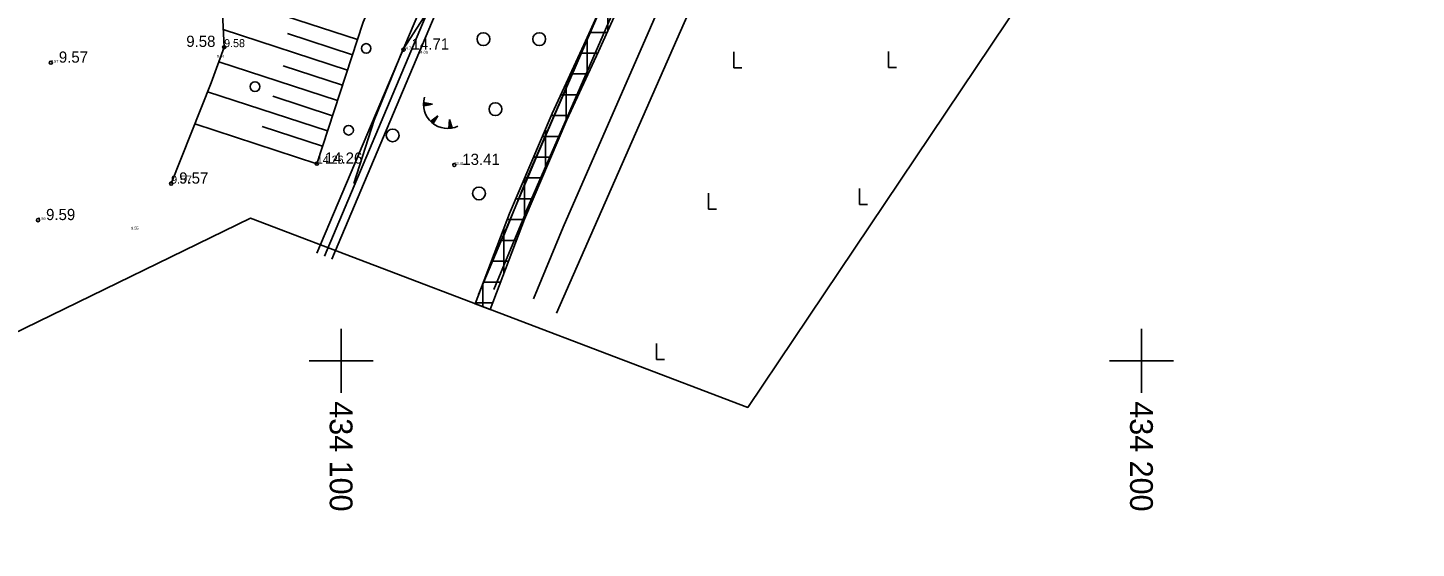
# Model space of a CAD drawing. Extents: x 433497 to 434382, y 6534486 to 6534993.
# Drawn here: x 434060.9 to 434234.3, y 6534676.6 to 6534741.6 of the extents above; entities that cross this region are included whole.
import ezdxf

# ---------------------------------------------------------------- set-up
doc = ezdxf.new("R2010")
doc.units = 0
for name, color, linetype in [('HALJASTUS', 7, 'Continuous'), ('Kaitsevöönd', 7, 'Continuous'), ('kataster', 7, 'Continuous'), ('KORGUS-EH2000', 7, 'Continuous'), ('MOOTKORG-EH2000', 7, 'Continuous'), ('PIIR', 7, 'Continuous'), ('RELJEEF', 7, 'Continuous'), ('TEE', 7, 'Continuous'), ('VORK', 7, 'Continuous'), ('VORMISTUS', 7, 'Continuous')]:
    doc.layers.add(name, color=color, linetype=linetype)

msp = doc.modelspace()

# ---------------------------------------------------------------- linework, layer by layer
at = {"layer": 'HALJASTUS'}
for p, q in [((434149.09, 6534738.6), (434149.09, 6534736.6)), ((434168.39, 6534738.64), (434168.39, 6534736.64)), ((434149.09, 6534736.6), (434150.09, 6534736.6)), ((434168.39, 6534736.64), (434169.39, 6534736.64)), ((434145.91, 6534720.93), (434145.91, 6534718.93)), ((434164.77, 6534721.53), (434164.77, 6534719.53)), ((434145.91, 6534718.93), (434146.91, 6534718.93)), ((434164.77, 6534719.53), (434165.77, 6534719.53)), ((434139.4, 6534702.16), (434139.4, 6534700.16)), ((434139.4, 6534700.16), (434140.4, 6534700.16))]:
    msp.add_line(p, q, dxfattribs=at)
msp.add_lwpolyline([(434120.17, 6534715.22), (434123.29, 6534722.97), (434138.26, 6534757.49), (434144.61, 6534770.46), (434146.07, 6534772.24), (434145.28, 6534773.04), (434138, 6534768.94), (434126.49, 6534763.78), (434119.61, 6534756.79), (434114.78, 6534749.84), (434107.73, 6534738.86), (434104.13, 6534730.07), (434101.6, 6534722.14)], dxfattribs=at)
for centre, radius in [((434103.14, 6534739.03), 0.6), ((434117.79, 6534740.19), 0.8), ((434124.76, 6534740.19), 0.8), ((434089.24, 6534734.26), 0.6), ((434119.29, 6534731.44), 0.8), ((434100.94, 6534728.81), 0.6), ((434106.44, 6534728.16), 0.8), ((434117.24, 6534720.91), 0.8)]:
    msp.add_circle(centre, radius, dxfattribs=at)
at = {"layer": 'Kaitsevöönd'}
for p, q in [((434133.33, 6534741.22), (434133.33, 6534746.11)), ((434131.06, 6534741.04), (434133.25, 6534741.04)), ((434130.73, 6534735.52), (434130.73, 6534740.31)), ((434129.88, 6534738.44), (434132.08, 6534738.44)), ((434128.68, 6534735.84), (434130.88, 6534735.84)), ((434128.13, 6534729.88), (434128.13, 6534734.66)), ((434127.47, 6534733.24), (434129.68, 6534733.24)), ((434126.28, 6534730.64), (434128.47, 6534730.64)), ((434125.53, 6534723.82), (434125.53, 6534728.89)), ((434125.16, 6534728.04), (434127.34, 6534728.04)), ((434124.05, 6534725.44), (434126.22, 6534725.44)), ((434122.93, 6534722.84), (434125.11, 6534722.84)), ((434122.93, 6534717.76), (434122.93, 6534722.83)), ((434121.82, 6534720.24), (434123.99, 6534720.24)), ((434120.74, 6534717.64), (434122.88, 6534717.64)), ((434119.76, 6534715.04), (434121.9, 6534715.04)), ((434120.33, 6534710.9), (434120.33, 6534716.56)), ((434118.77, 6534712.44), (434120.91, 6534712.44)), ((434117.79, 6534709.84), (434119.93, 6534709.84)), ((434117.73, 6534706.77), (434117.73, 6534709.68)), ((434116.77, 6534707.13), (434118.63, 6534706.42)), ((434116.81, 6534707.24), (434118.94, 6534707.24))]:
    msp.add_line(p, q, dxfattribs=at)
for points in [[(434128.22, 6534730.09), (434132.17, 6534738.64), (434136.03, 6534747.25), (434138.36, 6534752.33), (434142.93, 6534762.75), (434145.46, 6534769.14), (434146.37, 6534771.61), (434148.65, 6534776.78), (434150.92, 6534781.96), (434153.22, 6534787.21), (434154.72, 6534791.75), (434156.63, 6534795.9), (434159.88, 6534804.56), (434163.81, 6534814.84), (434168.18, 6534825.41), (434171.94, 6534834.07), (434175.51, 6534841.48), (434180.59, 6534850.69), (434185.97, 6534861.25), (434188.69, 6534866.23), (434193.78, 6534875.18), (434200.73, 6534887.95), (434203.32, 6534892.68)], [(434134.21, 6534748.07), (434130.35, 6534739.46), (434126.39, 6534730.89), (434121.03, 6534718.41), (434116.77, 6534707.13)], [(434118.63, 6534706.42), (434122.9, 6534717.68), (434128.22, 6534730.09)]]:
    msp.add_lwpolyline(points, dxfattribs=at)
at = {"layer": 'kataster'}
for points in [[(434117.18, 6534708.3), (434124.43, 6534725.5), (434148.55, 6534781.24), (434178.98, 6534849.69), (434202.39, 6534892.23)], [(434218.02, 6534802.56), (434170.81, 6534805.85), (434126.93, 6534705.93)]]:
    msp.add_lwpolyline(points, dxfattribs=at)
at = {"layer": 'KORGUS-EH2000'}
for centre in [(434085.39, 6534739.19), (434107.81, 6534738.88), (434063.74, 6534737.25), (434096.97, 6534724.63), (434114.15, 6534724.47), (434078.77, 6534722.14), (434062.14, 6534717.58)]:
    msp.add_circle(centre, 0.2, dxfattribs=at)
at = {"layer": 'PIIR'}
for points in [[(434096.98, 6534713.46), (434111.2, 6534747.09), (434125.92, 6534777.86), (434134.17, 6534794.4)], [(434097.91, 6534713.07), (434112.11, 6534746.68), (434126.82, 6534777.42), (434134.89, 6534793.6)], [(434098.83, 6534712.69), (434113.02, 6534746.27), (434127.72, 6534776.99), (434136.48, 6534794.54)]]:
    msp.add_lwpolyline(points, dxfattribs=at)
at = {"layer": 'RELJEEF'}
for p, q in [((434102.04, 6534740.13), (434085.33, 6534745.59)), ((434100.8, 6534736.33), (434085.28, 6534741.4)), ((434093.3, 6534740.88), (434101.42, 6534738.23)), ((434099.55, 6534732.52), (434084.73, 6534737.37)), ((434092.78, 6534736.84), (434100.18, 6534734.42)), ((434098.31, 6534728.72), (434083.32, 6534733.62)), ((434091.49, 6534733.06), (434098.93, 6534730.62)), ((434111.42, 6534732.05), (434110.3, 6534732.27)), ((434110.3, 6534732.2), (434110.37, 6534732.26)), ((434110.3, 6534732.14), (434110.43, 6534732.24)), ((434110.3, 6534732.07), (434110.49, 6534732.23)), ((434110.3, 6534732.01), (434110.56, 6534732.22)), ((434110.3, 6534731.95), (434110.62, 6534732.21)), ((434110.3, 6534731.88), (434110.69, 6534732.19)), ((434111.42, 6534732.05), (434110.3, 6534731.84)), ((434110.32, 6534731.84), (434110.75, 6534732.18)), ((434110.43, 6534731.86), (434110.82, 6534732.17)), ((434110.54, 6534731.88), (434110.88, 6534732.16)), ((434110.64, 6534731.9), (434110.95, 6534732.14)), ((434110.75, 6534731.92), (434111.01, 6534732.13)), ((434110.85, 6534731.94), (434111.07, 6534732.12)), ((434110.96, 6534731.96), (434111.14, 6534732.11)), ((434111.07, 6534731.99), (434111.2, 6534732.09)), ((434111.17, 6534732.01), (434111.27, 6534732.08)), ((434112.08, 6534730.61), (434111.19, 6534729.91)), ((434111.28, 6534732.03), (434111.33, 6534732.07)), ((434112.08, 6534730.61), (434111.52, 6534729.63)), ((434096.97, 6534724.63), (434081.73, 6534729.61)), ((434090.14, 6534729.29), (434097.69, 6534726.82)), ((434111.24, 6534729.86), (434111.24, 6534729.95)), ((434111.29, 6534729.82), (434111.29, 6534729.99)), ((434111.34, 6534729.78), (434111.34, 6534730.03)), ((434111.38, 6534729.73), (434111.4, 6534730.07)), ((434111.43, 6534729.7), (434111.45, 6534730.11)), ((434111.48, 6534729.66), (434111.5, 6534730.15)), ((434111.53, 6534729.65), (434111.55, 6534730.19)), ((434111.58, 6534729.74), (434111.6, 6534730.23)), ((434111.64, 6534729.83), (434111.65, 6534730.28)), ((434111.69, 6534729.93), (434111.7, 6534730.32)), ((434111.74, 6534730.02), (434111.76, 6534730.36)), ((434111.8, 6534730.12), (434111.81, 6534730.4)), ((434111.85, 6534730.21), (434111.86, 6534730.44)), ((434111.9, 6534730.3), (434111.91, 6534730.48)), ((434111.96, 6534730.4), (434111.96, 6534730.52)), ((434112.01, 6534730.49), (434112.01, 6534730.56)), ((434113.54, 6534730.17), (434113.46, 6534729.03)), ((434113.53, 6534729.04), (434113.46, 6534729.1)), ((434113.66, 6534729.05), (434113.47, 6534729.23)), ((434113.59, 6534729.04), (434113.47, 6534729.16)), ((434113.78, 6534729.07), (434113.48, 6534729.36)), ((434113.72, 6534729.06), (434113.48, 6534729.3)), ((434113.88, 6534729.11), (434113.49, 6534729.49)), ((434113.84, 6534729.08), (434113.49, 6534729.43)), ((434113.82, 6534729.31), (434113.5, 6534729.62)), ((434113.85, 6534729.21), (434113.5, 6534729.56)), ((434113.75, 6534729.52), (434113.51, 6534729.75)), ((434113.78, 6534729.41), (434113.51, 6534729.69)), ((434113.69, 6534729.72), (434113.52, 6534729.88)), ((434113.72, 6534729.62), (434113.52, 6534729.82)), ((434113.62, 6534729.93), (434113.53, 6534730.02)), ((434113.65, 6534729.83), (434113.53, 6534729.95)), ((434113.54, 6534730.17), (434113.89, 6534729.09)), ((434113.59, 6534730.03), (434113.54, 6534730.08))]:
    msp.add_line(p, q, dxfattribs=at)
for points in [[(434129.41, 6534765.84), (434122.95, 6534765.01), (434118.16, 6534761.86), (434113.49, 6534758.38), (434108.22, 6534753.42), (434105.41, 6534748.46), (434102.76, 6534742.33), (434096.97, 6534724.63)], [(434078.77, 6534722.14), (434083.76, 6534734.73), (434085.39, 6534739.19), (434085.15, 6534744.27), (434085.55, 6534747.13), (434086.6, 6534750.63), (434088.2, 6534754.58), (434090.45, 6534762.42), (434094.01, 6534764.84)]]:
    msp.add_lwpolyline(points, dxfattribs=at)
msp.add_arc((434113.32, 6534732.06), 3.03, 163.4234, 295.1745, dxfattribs=at)
at = {"layer": 'TEE'}
for points in [[(434119.09, 6534708.9), (434123.12, 6534718.63), (434123.12, 6534718.64), (434123.13, 6534718.66), (434123.14, 6534718.68), (434134.06, 6534743.67), (434144.32, 6534767.16), (434146.02, 6534771.11)], [(434150.71, 6534769.33), (434148.93, 6534765.18), (434148.93, 6534765.18), (434148.92, 6534765.17), (434148.92, 6534765.17), (434138.66, 6534741.66), (434138.66, 6534741.66), (434127.75, 6534716.7), (434124.04, 6534707.73)]]:
    msp.add_lwpolyline(points, dxfattribs=at)
at = {"layer": 'VORK'}
for p, q in [((434100, 6534704), (434100, 6534696)), ((434200, 6534704), (434200, 6534696)), ((434096, 6534700), (434104, 6534700)), ((434196, 6534700), (434204, 6534700))]:
    msp.add_line(p, q, dxfattribs=at)
at = {"layer": 'VORMISTUS'}
msp.add_lwpolyline([(434004.05, 6534676.58), (434088.7, 6534717.82), (434150.82, 6534694.17), (434223.11, 6534801.87), (434234.34, 6534880.46), (434217.51, 6534886.64), (434161.53, 6534910.47), (434143, 6534925.08), (434107.19, 6534919.58), (434105.08, 6534919.64), (434021.47, 6534961.7)], dxfattribs=at)
msp.add_lwpolyline([(434004.05, 6534676.58), (434088.7, 6534717.82), (434150.82, 6534694.17), (434223.11, 6534801.87), (434234.34, 6534880.46), (434217.51, 6534886.64), (434161.53, 6534910.47), (434143, 6534925.08), (434107.19, 6534919.58), (434105.08, 6534919.64), (434021.47, 6534961.7)], dxfattribs=at)

# ---------------------------------------------------------------- texts
at = {"layer": 'KORGUS-EH2000'}
for s, p in [('9.58', (434080.66, 6534739.22)), ('14.71', (434108.81, 6534738.88)), ('9.57', (434064.74, 6534737.25)), ('14.26', (434097.97, 6534724.63)), ('13.41', (434115.15, 6534724.47)), ('9.57', (434079.77, 6534722.14)), ('9.59', (434063.14, 6534717.58))]:
    msp.add_text(s, height=1.4, dxfattribs=at).set_placement(p)
at = {"layer": 'MOOTKORG-EH2000'}
for s, height, p in [('9.58', 1, (434085.39, 6534739.19)), ('9.57', 0.35, (434063.74, 6534737.25)), ('9.54', 0.35, (434084.46, 6534737.86)), ('14.71', 0.35, (434107.81, 6534738.88)), ('14.09', 0.35, (434109.64, 6534738.38)), ('14.26', 1, (434096.97, 6534724.63)), ('13.41', 0.35, (434114.15, 6534724.47)), ('9.57', 1, (434078.77, 6534722.14)), ('9.59', 0.35, (434062.14, 6534717.58)), ('9.55', 0.35, (434073.77, 6534716.39))]:
    msp.add_text(s, height=height, dxfattribs=at).set_placement(p)
at = {"layer": 'VORK'}
for s, p in [(' 434 100', (434098.58, 6534696)), (' 434 200', (434198.58, 6534696))]:
    msp.add_text(s, height=2.85, rotation=270, dxfattribs=at).set_placement(p)

doc.saveas('drawing.dxf')
